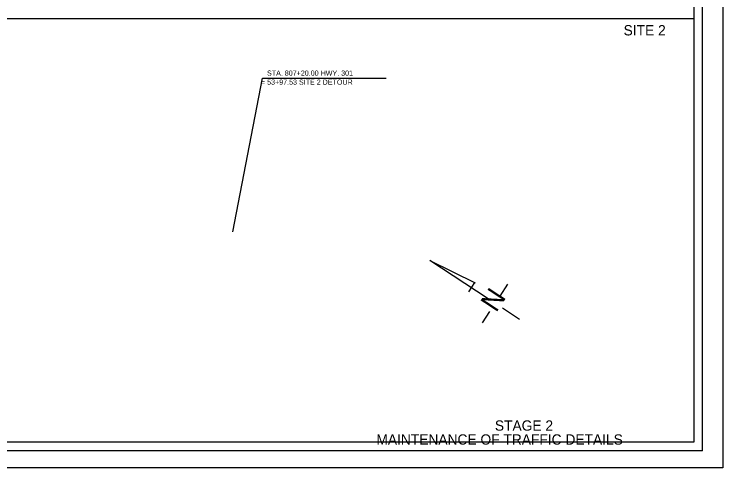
# Model space of a CAD drawing. Extents: x 1368648 to 1927880, y -1037443 to 380209.
# Drawn here: x 1376651 to 1377477, y 378686 to 379215 of the extents above; entities that cross this region are included whole.
import ezdxf

# ---------------------------------------------------------------- set-up
doc = ezdxf.new("R2010")
doc.units = 0
for name, color, linetype in [('R_Border', 7, 'Continuous'), ('R_Border Title', 7, 'Continuous'), ('R_Detour Annot Limits', 7, 'Continuous'), ('R_Draft', 7, 'Continuous'), ('R_No Plot', 7, 'Continuous')]:
    doc.layers.add(name, color=color, linetype=linetype)

msp = doc.modelspace()

# ---------------------------------------------------------------- linework, layer by layer
at = {"layer": 'R_Border'}
for q in [(1377453.08, 379733.26), (1375872.18, 378705.96)]:
    msp.add_line((1377453.08, 378705.96), q, dxfattribs=at)
at = {"layer": 'R_Detour Annot Limits'}
for p, q in [((1376906.07, 378960.98), (1376940.5, 379140.21)), ((1376940.5, 379140.21), (1377084.88, 379140.21))]:
    msp.add_line(p, q, dxfattribs=at)
at = {"layer": 'R_Draft'}
for p, q in [((1377135.67, 378927.45), (1377188.29, 378901.57)), ((1377203.65, 378882.77), (1377135.67, 378927.45)), ((1377180.83, 378891.01), (1377187.93, 378901.82)), ((1377217.31, 378886.08), (1377226.36, 378899.86)), ((1377196.97, 378855.14), (1377205.45, 378868.03)), ((1377240.12, 378858.8), (1377220.13, 378871.94))]:
    msp.add_line(p, q, dxfattribs=at)
at = {"layer": 'R_No Plot'}
for points in [[(1375810.14, 379752.73), (1377476.84, 379752.73), (1377476.84, 378686.04), (1375810.14, 378686.04)], [(1375882.18, 379723.26), (1377129.88, 379723.26), (1377129.88, 379673.86), (1377217.58, 379673.86), (1377338.08, 379673.86), (1377338.08, 379562.19), (1377443.08, 379562.19), (1377443.08, 378715.96), (1375882.18, 378715.96)], [(1375882.18, 379209.61), (1377443.08, 379209.61), (1377443.08, 378715.96), (1375882.18, 378715.96)], [(1375882.18, 379209.61), (1377443.08, 379209.61), (1377443.08, 378715.96), (1375882.18, 378715.96)], [(1375882.18, 379209.61), (1377443.08, 379209.61), (1377443.08, 378715.96), (1375882.18, 378715.96)], [(1375882.18, 379209.61), (1377443.08, 379209.61), (1377443.08, 378715.96), (1375882.18, 378715.96)], [(1375882.18, 379209.61), (1377443.08, 379209.61), (1377443.08, 378715.96), (1375882.18, 378715.96)], [(1375882.18, 379209.61), (1377443.08, 379209.61), (1377443.08, 378715.96), (1375882.18, 378715.96)], [(1375882.18, 379209.61), (1377443.08, 379209.61), (1377443.08, 378715.96), (1375882.18, 378715.96)]]:
    msp.add_lwpolyline(points, close=True, dxfattribs=at)

# ---------------------------------------------------------------- texts
at = {"layer": 'R_Border Title'}
for s, p in [('SITE 2', (1377361.28, 379189.84)), ('STAGE 2', (1377211.35, 378729.32)), ('MAINTENANCE OF TRAFFIC DETAILS', (1377073.32, 378713.07))]:
    msp.add_text(s, height=12, dxfattribs=at).set_placement(p)
at = {"layer": 'R_Detour Annot Limits'}
for s, p in [('STA. 807+20.00 HWY. 301', (1376945.95, 379142.94)), ('= 53+97.53 SITE 2 DETOUR', (1376938.93, 379132.44))]:
    msp.add_text(s, height=6, rotation=360, dxfattribs=at).set_placement(p)
at = {"layer": 'R_Draft'}
msp.add_text('N', height=23.27, rotation=56.6872, dxfattribs=at).set_placement((1377212.81, 378866.19))

doc.saveas('drawing.dxf')
